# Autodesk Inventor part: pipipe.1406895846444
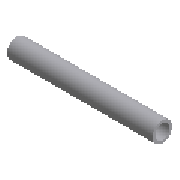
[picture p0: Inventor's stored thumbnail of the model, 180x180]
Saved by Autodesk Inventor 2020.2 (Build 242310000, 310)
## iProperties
Manager: www.cadconsulting.pl
Company: Fabian Stasiak CAD Consulting
IsCustomPart: 1
NAME: PIPING: JIS G 3458 Pipe
DATA: <meta><inlinegroups number="1" deflen="10"></inlinegroups><connections number="2"></connections><angles><a>3.14159265358979</a></angles></meta>
Created: 2014-02
Material: Stal, stopowa
Description: Rura
Document SubType Name: Modeling
Standard: JIS G 3458
Designer: F.Stasiak
Standards Organization: JIS
Language: pl-PL
Size Designation: 40 A x Sch 80 - 100
Categories: <MemberInstance><Categories><Category DisplayName="Rury cienko- i grubościenne" InternalName="4347fa0f-2144-441d-94cd-e3e15c92b736" Mnemonic="TUBEANDPIPE"><Cate
Stock Number: JIS G 3458 Rura 40 A x Sch 80
Density: 7.73 g/cm^3
Appearance: Częściowo polerowana
Catalog Web Link: www.expertbooks.pl
L: 118,000 mm
PL: 118,000 mm
Author: F.Stasiak
Subject: Zbiór ćwiczeń. Autodesk Inventor 2020. Kurs Professional
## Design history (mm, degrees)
sketch "Sketch1"
  geometry: C1 r 24.3 at (0, 0); C2 r 19.2 at (0, 0); 1 further point
  constraints: 2 centre point, 2 coincident, 1 concentric
  dimensions: "d0" = 48.6 diameter of C1 (= OD); "d1" = 38.4 diameter of C2 (= OD - 2 x t)
extrude "Extrusion1" new body sketch "Sketch1" distance "d2" = 118 (= L); taper "d3" = 0 deg
workaxis "Work Axis1"
workpoint "Work Point1"
workaxis "Work Axis2"
workpoint "Work Point2"
body "Solid1"
other parameters: "OD" = 48.6 [user parameter; used in 2 equation terms], "t" = 5.1 [user parameter; used in 1 equation term], "L" = 118 (= PL) [user parameter; used in 1 equation term], "ID" = 38.4 [user parameter], "PL" = 118 [user parameter; used in 1 equation term], "Size_Designation" = 12.345 [user parameter]
